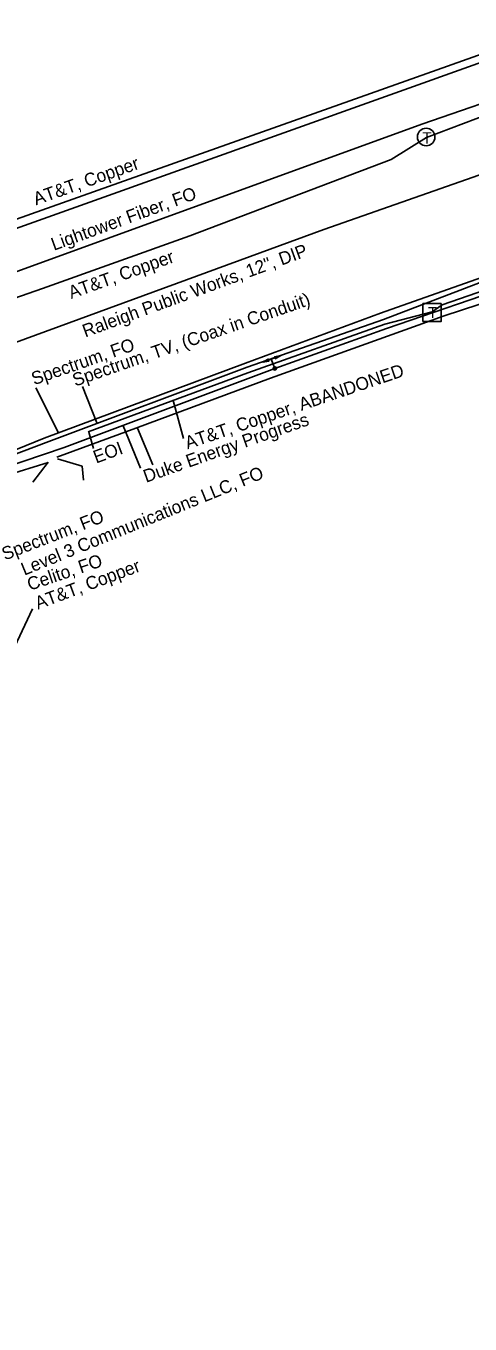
# Model space of a CAD drawing. Extents: x 2070721 to 2083340, y 729290 to 737883.
# Drawn here: x 2080810.4 to 2080947.7, y 734354.5 to 734755.4 of the extents above; entities that cross this region are included whole.
import ezdxf

# ---------------------------------------------------------------- set-up
doc = ezdxf.new("R2010")
doc.units = 0
for name, color, linetype in [('Exist Utilities Power Change of Service SUE CELL', 7, 'Continuous'), ('Exist Utilities Power UG Cable SUE LOS B', 7, 'Continuous'), ('Exist Utilities Power UG Cable SUE LOS B Leader', 7, 'Continuous'), ('Exist Utilities Power UG Cable SUE LOS B Text', 7, 'Continuous'), ('Exist Utilities Power UG Cable SUE LOS C', 7, 'Continuous'), ('Exist Utilities Telephone Hand Hole Leader', 7, 'Continuous'), ('Exist Utilities Telephone Hand Hole Text', 7, 'Continuous'), ('Exist Utilities Telephone Manhole CELL', 7, 'Continuous'), ('Exist Utilities Telephone Pedestal CELL', 7, 'Continuous'), ('Exist Utilities Telephone UG Cable SUE LOS C', 7, 'Continuous'), ('Exist Utilities Telephone UG Cable SUE LOS C Leader', 7, 'Continuous'), ('Exist Utilities Telephone UG Cable SUE LOS C Text', 7, 'Continuous'), ('Exist Utilities Telephone UG Conduit SUE LOS B', 7, 'Continuous'), ('Exist Utilities Telephone UG FO SUE LOS B', 7, 'Continuous'), ('Exist Utilities Telephone UG FO SUE LOS B Leader', 7, 'Continuous'), ('Exist Utilities Telephone UG FO SUE LOS B Text', 7, 'Continuous'), ('Exist Utilities Telephone UG FO SUE LOS C Text', 7, 'Continuous'), ('Exist Utilities TV UG Cable SUE LOS B', 7, 'Continuous'), ('Exist Utilities TV UG Cable SUE LOS B Leader', 7, 'Continuous'), ('Exist Utilities TV UG Cable SUE LOS B Text', 7, 'Continuous'), ('Exist Utilities TV UG FO Cable SUE LOS B', 7, 'Continuous'), ('Exist Utilities TV UG FO Cable SUE LOS B Text', 7, 'Continuous'), ('Exist Utilities Water UG Line SUE LOS B', 7, 'Continuous'), ('Exist Utilities Water UG Line SUE LOS B Text', 7, 'Continuous')]:
    doc.layers.add(name, color=color, linetype=linetype)

msp = doc.modelspace()

# ---------------------------------------------------------------- linework, layer by layer
at = {"layer": 'Exist Utilities Power Change of Service SUE CELL'}
for p, q in [((2080889.19, 734653.64), (2080883.61, 734651.54)), ((2080886.25, 734652.54), (2080889.19, 734653.64)), ((2080887.34, 734649.65), (2080886.25, 734652.54)), ((2080887.34, 734649.65), (2080887.34, 734649.65))]:
    msp.add_line(p, q, dxfattribs=at)
for points in [[(2080883.61, 734651.54), (2080885.33, 734652.56), (2080885.06, 734652.09), (2080885.52, 734651.94)], [(2080889.19, 734653.64), (2080887.46, 734652.62), (2080887.74, 734653.09), (2080887.27, 734653.24)]]:
    msp.add_lwpolyline(points, close=True, dxfattribs=at)
msp.add_circle((2080887.34, 734649.65), 0.517, dxfattribs=at)
at = {"layer": 'Exist Utilities Power UG Cable SUE LOS B'}
msp.add_line((2080817.31, 734620.69), (2080812.59, 734614.55), dxfattribs=at)
for points in [[(2080820, 734622.29), (2080844.38, 734631.25), (2080886.06, 734646.68), (2080939.66, 734665.94), (2080971.55, 734676.3), (2081034.15, 734699.4), (2081093.26, 734724.52), (2081121.49, 734735.79), (2081125.29, 734737.91), (2081128.97, 734740.08), (2081128.97, 734740.08)], [(2080887.34, 734649.65), (2080921.88, 734661.96), (2080962.1, 734675.79), (2081000.33, 734689.04), (2081037.16, 734702.37)], [(2080667.78, 734563.47), (2080675.81, 734558.73), (2080709.93, 734583.03), (2080741.96, 734594.47), (2080777.33, 734608.24), (2080817.29, 734620.64)], [(2080820.22, 734621.7), (2080827.8, 734619.42), (2080828.24, 734615.15)]]:
    msp.add_lwpolyline(points, dxfattribs=at)
at = {"layer": 'Exist Utilities Power UG Cable SUE LOS B Leader'}
for p, q in [((2080840.5, 734631.96), (2080845.82, 734618.86)), ((2080844.88, 734631.24), (2080849.68, 734619.84))]:
    msp.add_line(p, q, dxfattribs=at)
at = {"layer": 'Exist Utilities Power UG Cable SUE LOS C'}
for points in [[(2080186.05, 734475.29), (2080187.03, 734475.63), (2080448.94, 734565.1), (2080663.08, 734641.37), (2080827.26, 734699.95), (2080984.4, 734756.05), (2081109.44, 734801.16), (2081210.88, 734831.9), (2081586.98, 734944.46), (2081830.55, 735019.69), (2082038.54, 735143.44), (2082248.34, 735270.09)], [(2080667.78, 734563.47), (2080684.69, 734572.51), (2080703.86, 734583.33), (2080803.07, 734618.73), (2080822.19, 734625.25), (2080887.34, 734649.65)]]:
    msp.add_lwpolyline(points, dxfattribs=at)
at = {"layer": 'Exist Utilities Telephone Hand Hole Leader'}
msp.add_line((2080829.88, 734629.94), (2080831.35, 734624.97), dxfattribs=at)
at = {"layer": 'Exist Utilities Telephone Manhole CELL'}
msp.add_circle((2080934.12, 734721.13), 2.72, dxfattribs=at)
at = {"layer": 'Exist Utilities Telephone Pedestal CELL'}
msp.add_line((2080935.84, 734666.93), (2080935.84, 734666.93), dxfattribs=at)
msp.add_lwpolyline([(2080933.12, 734664.1), (2080938.71, 734664.1), (2080938.71, 734669.7), (2080933.12, 734669.7), (2080933.12, 734664.1)], dxfattribs=at)
at = {"layer": 'Exist Utilities Telephone UG Cable SUE LOS C'}
for points in [[(2080527.18, 734594.58), (2080756.63, 734677.7), (2080975.53, 734755.33), (2081114.85, 734806.49), (2081251.31, 734880.3), (2081357.91, 734934.96), (2081407.46, 734955.63), (2081557.34, 735013.56), (2081611.19, 735031.21), (2081670.8, 735036.79), (2081727.82, 735033.26), (2081796.62, 735020.83), (2081876.61, 734998.57), (2081913.61, 734982.12), (2081940.08, 734960.79), (2081955.36, 734908.6), (2081940.34, 734844.38), (2081917.15, 734795.51)], [(2080934.26, 734720.97), (2081041, 734761.39), (2081061.56, 734773.15), (2081150.65, 734813.71), (2081201.33, 734846.96), (2081300.64, 734903.05), (2081400.2, 734948.86), (2081476.71, 734979.23), (2081590.79, 735021.91), (2081620.53, 735029.68), (2081685.91, 735033.08), (2081745.92, 735027.46), (2081824.22, 735009.88), (2081875.43, 734995.15), (2081909.49, 734979.28), (2081909.49, 734966.35), (2081906.46, 734953.04)], [(2080829.69, 734630.12), (2080879.03, 734648.33), (2080921.3, 734663.31), (2080935.93, 734667.09), (2080939.07, 734669.34), (2080979.29, 734683.22), (2081029.96, 734701.46), (2081063.22, 734714.57)]]:
    msp.add_lwpolyline(points, dxfattribs=at)
at = {"layer": 'Exist Utilities Telephone UG Cable SUE LOS C Leader'}
for p, q in [((2080855.94, 734639.74), (2080859.08, 734628.02)), ((2080793.04, 734534.25), (2080812.48, 734575.36))]:
    msp.add_line(p, q, dxfattribs=at)
at = {"layer": 'Exist Utilities Telephone UG Conduit SUE LOS B'}
msp.add_lwpolyline([(2080232.24, 734245.67), (2080237.5, 734254.36), (2080238.66, 734282.35), (2080245.75, 734323.83), (2080258.86, 734369.55), (2080269.86, 734398.57), (2080309.08, 734449.32), (2080323.63, 734464.88), (2080355.41, 734492.16), (2080379.52, 734509.8), (2080416.03, 734529.49), (2080502.71, 734562.3), (2080573.96, 734587.12), (2080616.57, 734603.22), (2080677.16, 734624.99), (2080749, 734651.22), (2080815.57, 734674.3), (2080861.11, 734690.56), (2080923.26, 734714.15), (2080934.26, 734720.97)], dxfattribs=at)
at = {"layer": 'Exist Utilities Telephone UG FO SUE LOS B'}
msp.add_lwpolyline([(2080717.24, 734648.01), (2080746.66, 734657.69), (2080787.43, 734672.3), (2080932.78, 734725.13), (2080966.26, 734736.59)], dxfattribs=at)
at = {"layer": 'Exist Utilities Telephone UG FO SUE LOS B Leader'}
msp.add_line((2080820.47, 734629.78), (2080813.43, 734643.61), dxfattribs=at)
at = {"layer": 'Exist Utilities TV UG Cable SUE LOS B'}
msp.add_lwpolyline([(2080540.63, 734520.42), (2080564.59, 734528.02), (2080616.67, 734550.17), (2080656.9, 734568.75), (2080683.34, 734575.14), (2080742.18, 734595.53), (2080780.96, 734613.32), (2080816.71, 734626.79), (2080878.8, 734650.08), (2080920.95, 734664.77), (2080961.27, 734680.22)], dxfattribs=at)
at = {"layer": 'Exist Utilities TV UG Cable SUE LOS B Leader'}
msp.add_line((2080832.35, 734632.82), (2080827.87, 734644.08), dxfattribs=at)
at = {"layer": 'Exist Utilities TV UG FO Cable SUE LOS B'}
msp.add_lwpolyline([(2080783.05, 734614.76), (2080816.08, 734628.1), (2080878.27, 734651.3), (2080919.99, 734666.74), (2080989.43, 734691.22), (2081068.18, 734719.46), (2081106.14, 734736.11), (2081119.77, 734739.04)], dxfattribs=at)
at = {"layer": 'Exist Utilities Water UG Line SUE LOS B'}
msp.add_lwpolyline([(2080357.06, 734003.27), (2080353.32, 734006.79), (2080296.63, 734072.2), (2080261.95, 734141.13), (2080251.22, 734185.42), (2080250, 734189.2), (2080244.12, 734248.6), (2080244.13, 734251.5), (2080244.63, 734259.68), (2080245.13, 734264.1), (2080254.44, 734320.44), (2080276.53, 734380.91), (2080391.41, 734503.18), (2080497.9, 734548.7), (2080500.72, 734549.83), (2080585.45, 734578.7), (2080702.53, 734619.89), (2080710.17, 734622.62), (2080743.51, 734634.52), (2080754.26, 734638.28), (2080902.52, 734692.58), (2081024.44, 734735.33)], dxfattribs=at)

# ---------------------------------------------------------------- texts
at = {"layer": 'Exist Utilities Power UG Cable SUE LOS B Text'}
msp.add_text('Duke Energy Progress', height=4, rotation=19.4936, dxfattribs=at).set_placement((2080847.54, 734614.31))
at = {"layer": 'Exist Utilities Telephone Hand Hole Text'}
msp.add_text('EOI', height=4, rotation=20.4341, dxfattribs=at).set_placement((2080832.13, 734620.24))
at = {"layer": 'Exist Utilities Telephone Manhole CELL'}
msp.add_text('T', height=3.5, dxfattribs=at).set_placement((2080932.95, 734719.12))
at = {"layer": 'Exist Utilities Telephone Pedestal CELL'}
msp.add_text('T', height=3.42, dxfattribs=at).set_placement((2080934.71, 734665.21))
at = {"layer": 'Exist Utilities Telephone UG Cable SUE LOS C Text'}
for s, rotation, p in [('AT&T, Copper', 19.5258, (2080813.52, 734700)), ('AT&T, Copper', 19.649, (2080824.39, 734671.08)), ('AT&T, Copper, ABANDONED', 18.6897, (2080860.36, 734624.63)), ('AT&T, Copper', 20.4865, (2080814.12, 734575.14))]:
    msp.add_text(s, height=4, rotation=rotation, dxfattribs=at).set_placement(p)
at = {"layer": 'Exist Utilities Telephone UG FO SUE LOS B Text'}
for s, rotation, p in [('Lightower Fiber, FO', 19.9746, (2080819.07, 734685.97)), ('Spectrum, FO ', 19.1427, (2080812.94, 734644.45)), ('Level 3 Communications LLC, FO', 22.1458, (2080809.92, 734585.61))]:
    msp.add_text(s, height=4, rotation=rotation, dxfattribs=at).set_placement(p)
at = {"layer": 'Exist Utilities Telephone UG FO SUE LOS C Text'}
msp.add_text('Celito, FO ', height=4, rotation=18.657, dxfattribs=at).set_placement((2080811.61, 734580.95))
at = {"layer": 'Exist Utilities TV UG Cable SUE LOS B Text'}
msp.add_text('Spectrum, TV, (Coax in Conduit)', height=4, rotation=19.1427, dxfattribs=at).set_placement((2080825.64, 734644.03))
at = {"layer": 'Exist Utilities TV UG FO Cable SUE LOS B Text'}
msp.add_text(' Spectrum, FO', height=4, rotation=21.2063, dxfattribs=at).set_placement((2080802.52, 734589.77))
at = {"layer": 'Exist Utilities Water UG Line SUE LOS B Text'}
msp.add_text('Raleigh Public Works, 12", DIP', height=4, rotation=20.1152, dxfattribs=at).set_placement((2080828.76, 734659.18))

doc.saveas('drawing.dxf')
